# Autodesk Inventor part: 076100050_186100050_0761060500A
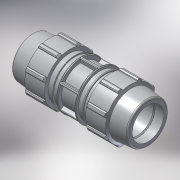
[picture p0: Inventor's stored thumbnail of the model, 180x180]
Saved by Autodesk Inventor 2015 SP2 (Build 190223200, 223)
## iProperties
Created: 2017-02
Part Number: 076100050_186100050_0761060500A
Material: PVC-Piping
Description: PLASSON REPAIR COUPLER 50
Document SubType Name: Modeling
Designer: KIM
Mass: 8658.36 g
Surface Area: 5623.3 cm^2
Volume: 6184.54 cm^3
Density: 1.4 g/cm^3
Appearance: Smooth - White
Author: KIM
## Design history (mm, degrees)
derived "07610.ipt"
feature "Solid1::07610.ipt"
tag "TaggingFeature1"
body "Solid1"
other parameters: "d1" = 244, "d4" = 20.33333, "d5" = 34.85714, "d7" = 96, "d8" = 72, "d9" = 34.85714, "d11" = 3.48571, "d12" = 76.8, "d13" = 120 deg, "d14" = 75, "d15" = 8 deg, "d16" = 86.4, "d18" = 2.5, "d19" = 35 deg, "d20" = 17.5 deg, "d21" = 89.28, "d23" = 0, "d25" = 360 deg, "d27" = 1.92, "d33" = 1, "d34" = 4.8, "d36" = 0, "d37" = 1, "d38" = 1, "d40" = 360 deg, "d42" = 43.92, "d43" = 2.88, "d46" = 1.5, "d50" = 9.41143, "d51" = 76.8, "E_" = 96, "H_" = 244, "l_" = 158, "d49" = 22.30857
